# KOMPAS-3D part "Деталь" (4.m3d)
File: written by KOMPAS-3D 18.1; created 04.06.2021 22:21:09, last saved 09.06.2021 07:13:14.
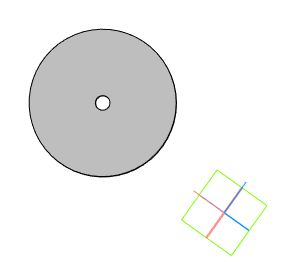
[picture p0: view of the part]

Document properties: Автор: 111; Полное имя файла: C:\Users\admin\Desktop\ffb\4.m3d

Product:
- Part/product: Деталь
    Масса: 1.75922

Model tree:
1. Эскиз:1
2. Элемент выдавливания:1
     Расстояние 1 = 20
3. Элемент выдавливания:2
     Расстояние 2 = 10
